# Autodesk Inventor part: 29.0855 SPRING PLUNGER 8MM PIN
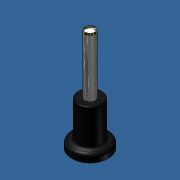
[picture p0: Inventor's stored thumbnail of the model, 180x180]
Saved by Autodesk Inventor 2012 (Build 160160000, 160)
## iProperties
Created: 2016-09
Part Number: 29.0855 SPRING PLUNGER 8MM PIN
Material: Steel
Document SubType Name: Modeling
Designer: Admin
Density: 7.85 g/cm^3
Mass: 109.362 g
Surface Area: 43.1523 cm^2
Volume: 13.9314 cm^3
Author: Admin
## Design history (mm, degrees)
feature "Base1"
sketch "Sketch1"
  geometry: L1 (-9.815, 0)-(-4.907, 8.5); L2 (-4.907, 8.5)-(4.907, 8.5); L3 (4.907, 8.5)-(9.815, 0); L4 (9.815, 0)-(4.907, -8.5); L5 (4.907, -8.5)-(-4.907, -8.5); L6 (-4.907, -8.5)-(-9.815, 0); C1 r 8.5 at (0, 0) reference; 2 further points
  constraints: 12 end point, 5 equal length, 2 horizontal, 2 horizontal alignment, 2 midpoint, 2 vertical alignment
  dimensions: "d0" = 120 deg angle of L1 L2; "d1" = 120 deg angle of L3 L2 (derived); "d2" = 120 deg angle of L6 L1 (derived); "d3" = 120 deg angle of L5 L6 (derived); "d4" = 120 deg angle of L4 L5 (derived); "d5" = 120 deg angle of L4 L3 (derived); "d6" = 17 distance between parallel lines of L5 L2
extrude "Extrusion1" join sketch "Sketch1" distance "d7" = 8; taper "d8" = 0 deg
sketch "Sketch2"
  geometry: C1 r 4 at (0, 0) reference; C2 r 24.171 at (0, 0)
  constraints: 1 centre point, 1 coincident
extrude "Extrusion2" cut sketch "Sketch2" stored distance "d9" = 10; taper "d10" = 0 deg
body "Solid1"
